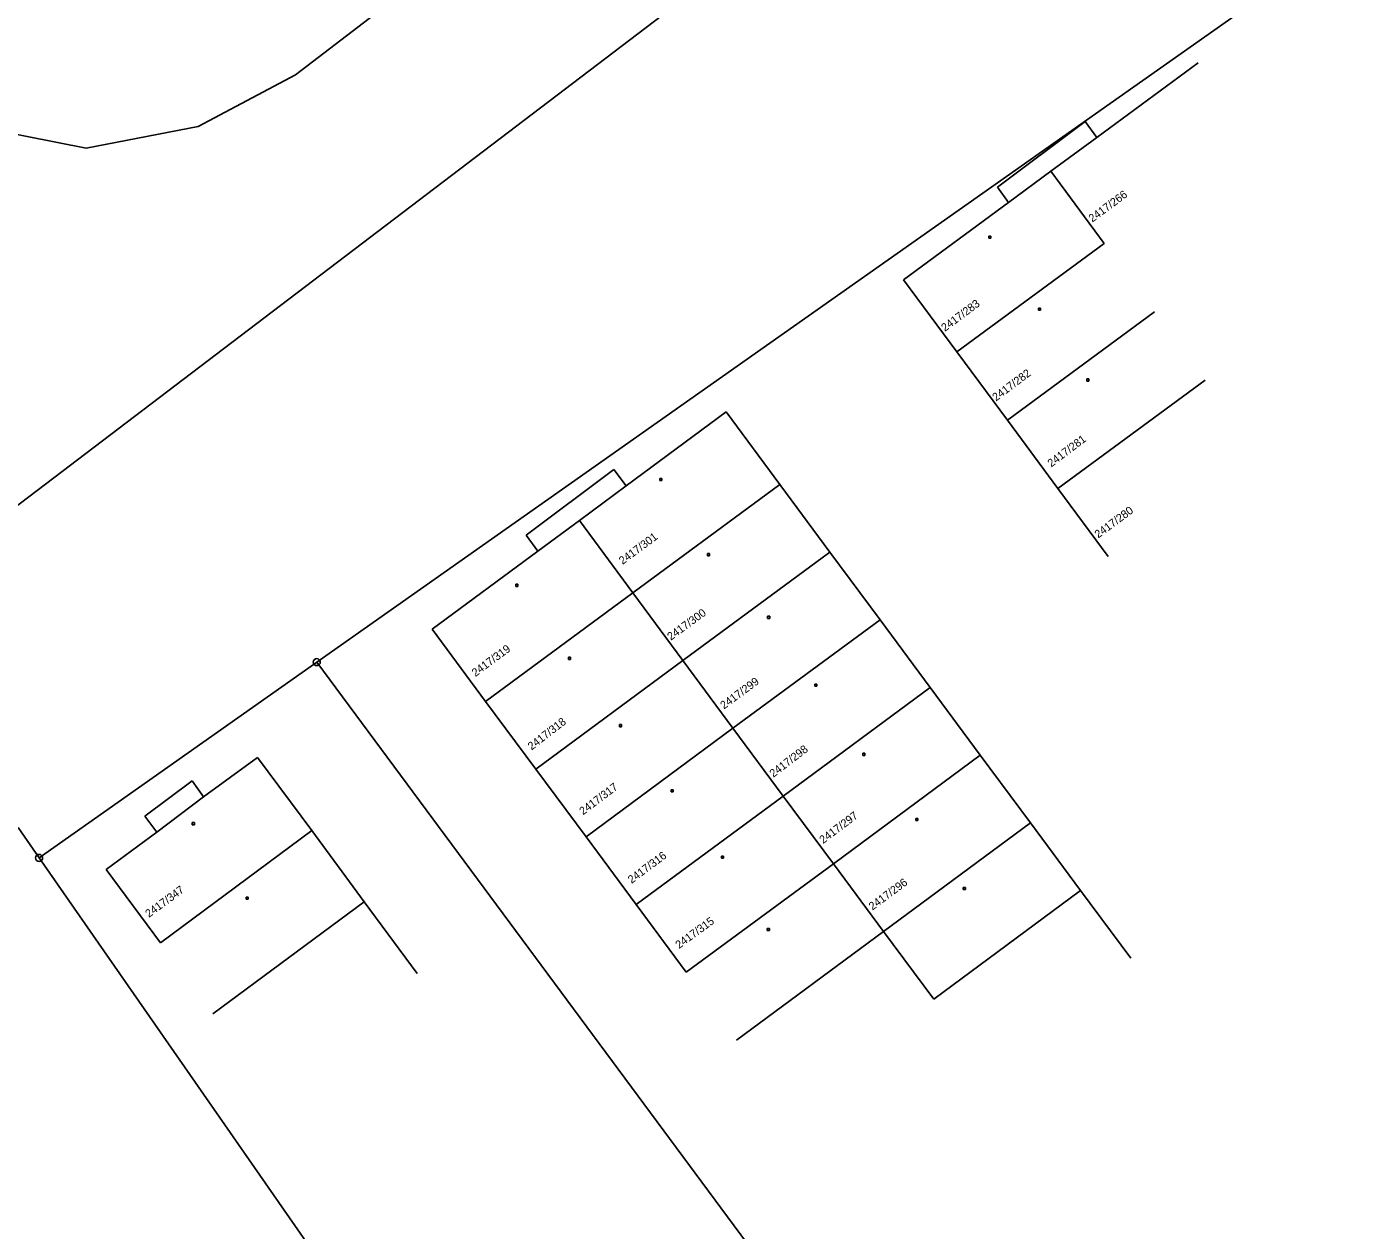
# Model space of a CAD drawing. Extents: x -609709 to -609357, y -1051535 to -1051131.
# Drawn here: x -609457.42 to -609409.61, y -1051497.4 to -1051454.54 of the extents above; entities that cross this region are included whole.
import ezdxf

# ---------------------------------------------------------------- set-up
doc = ezdxf.new("R2010")
doc.units = 0
doc.layers.add('Vrstva 10', color=7, linetype='Continuous')

msp = doc.modelspace()

# ---------------------------------------------------------------- linework, layer by layer
at = {"layer": 'Vrstva 10'}
for p, q in [((-609463.64, -1051476.07), (-609422.08, -1051444.46)), ((-609434.44, -1051445.99), (-609447.85, -1051456.25)), ((-609447.09, -1051477.17), (-609409.61, -1051450.76)), ((-609419.31, -1051458.49), (-609415.7, -1051455.83)), ((-609451.32, -1051458.09), (-609447.85, -1051456.25)), ((-609422.85, -1051460.26), (-609419.72, -1051457.92)), ((-609419.72, -1051457.92), (-609419.31, -1051458.49)), ((-609459.22, -1051458.09), (-609455.3, -1051458.86)), ((-609455.3, -1051458.86), (-609451.32, -1051458.09)), ((-609420.95, -1051459.69), (-609419.31, -1051458.49)), ((-609422.46, -1051460.8), (-609420.95, -1051459.69)), ((-609420.95, -1051459.69), (-609419.05, -1051462.26)), ((-609422.85, -1051460.26), (-609422.46, -1051460.8)), ((-609426.19, -1051463.55), (-609422.46, -1051460.8)), ((-609424.29, -1051466.12), (-609419.05, -1051462.26)), ((-609423.155, -1051461.995), (-609423.08, -1051461.995)), ((-609423.155, -1051462.07), (-609423.155, -1051461.995)), ((-609423.08, -1051462.07), (-609423.155, -1051462.07)), ((-609423.08, -1051461.995), (-609423.08, -1051462.07)), ((-609426.19, -1051463.55), (-609424.29, -1051466.12)), ((-609422.49, -1051468.55), (-609417.25, -1051464.7)), ((-609421.385, -1051464.565), (-609421.31, -1051464.565)), ((-609421.385, -1051464.64), (-609421.385, -1051464.565)), ((-609421.31, -1051464.64), (-609421.385, -1051464.64)), ((-609421.31, -1051464.565), (-609421.31, -1051464.64)), ((-609424.29, -1051466.12), (-609422.49, -1051468.55)), ((-609420.7, -1051470.98), (-609415.45, -1051467.13)), ((-609419.665, -1051467.085), (-609419.59, -1051467.085)), ((-609419.665, -1051467.16), (-609419.665, -1051467.085)), ((-609419.59, -1051467.085), (-609419.59, -1051467.16)), ((-609419.59, -1051467.16), (-609419.665, -1051467.16)), ((-609436.07, -1051470.89), (-609432.51, -1051468.26)), ((-609432.51, -1051468.26), (-609430.6, -1051470.84)), ((-609422.49, -1051468.55), (-609420.7, -1051470.98)), ((-609439.63, -1051472.65), (-609436.51, -1051470.31)), ((-609436.51, -1051470.31), (-609436.07, -1051470.89)), ((-609437.74, -1051472.13), (-609436.07, -1051470.89)), ((-609435.84, -1051474.7), (-609430.6, -1051470.84)), ((-609434.875, -1051470.625), (-609434.8, -1051470.625)), ((-609434.875, -1051470.7), (-609434.875, -1051470.625)), ((-609434.8, -1051470.7), (-609434.875, -1051470.7)), ((-609434.8, -1051470.625), (-609434.8, -1051470.7)), ((-609430.6, -1051470.84), (-609428.82, -1051473.25)), ((-609420.7, -1051470.98), (-609418.9, -1051473.41)), ((-609439.22, -1051473.22), (-609437.74, -1051472.13)), ((-609437.74, -1051472.13), (-609435.84, -1051474.7)), ((-609439.63, -1051472.65), (-609439.22, -1051473.22)), ((-609442.98, -1051475.99), (-609439.22, -1051473.22)), ((-609434.05, -1051477.11), (-609428.82, -1051473.25)), ((-609433.175, -1051473.305), (-609433.1, -1051473.305)), ((-609433.175, -1051473.38), (-609433.175, -1051473.305)), ((-609433.1, -1051473.305), (-609433.1, -1051473.38)), ((-609428.82, -1051473.25), (-609427.03, -1051475.66)), ((-609433.1, -1051473.38), (-609433.175, -1051473.38)), ((-609441.08, -1051478.57), (-609435.84, -1051474.7)), ((-609440.005, -1051474.395), (-609439.93, -1051474.395)), ((-609440.005, -1051474.47), (-609440.005, -1051474.395)), ((-609439.93, -1051474.47), (-609440.005, -1051474.47)), ((-609439.93, -1051474.395), (-609439.93, -1051474.47)), ((-609435.84, -1051474.7), (-609434.05, -1051477.11)), ((-609432.27, -1051479.52), (-609427.03, -1051475.66)), ((-609431.035, -1051475.535), (-609430.96, -1051475.535)), ((-609431.035, -1051475.61), (-609431.035, -1051475.535)), ((-609430.96, -1051475.61), (-609431.035, -1051475.61)), ((-609430.96, -1051475.535), (-609430.96, -1051475.61)), ((-609427.03, -1051475.66), (-609425.24, -1051478.07)), ((-609442.98, -1051475.99), (-609441.08, -1051478.57)), ((-609456.98, -1051484.14), (-609447.09, -1051477.17)), ((-609447.09, -1051477.17), (-609411.09, -1051525.77)), ((-609439.29, -1051480.98), (-609434.05, -1051477.11)), ((-609438.125, -1051476.995), (-609438.05, -1051476.995)), ((-609438.125, -1051477.07), (-609438.125, -1051476.995)), ((-609438.05, -1051477.07), (-609438.125, -1051477.07)), ((-609438.05, -1051476.995), (-609438.05, -1051477.07)), ((-609434.05, -1051477.11), (-609432.27, -1051479.52)), ((-609430.48, -1051481.94), (-609425.24, -1051478.07)), ((-609429.355, -1051477.955), (-609429.28, -1051477.955)), ((-609429.355, -1051478.03), (-609429.355, -1051477.955)), ((-609429.28, -1051478.03), (-609429.355, -1051478.03)), ((-609429.28, -1051477.955), (-609429.28, -1051478.03)), ((-609425.24, -1051478.07), (-609423.46, -1051480.48)), ((-609441.08, -1051478.57), (-609439.29, -1051480.98)), ((-609437.5, -1051483.39), (-609432.27, -1051479.52)), ((-609436.315, -1051479.395), (-609436.24, -1051479.395)), ((-609436.315, -1051479.47), (-609436.315, -1051479.395)), ((-609436.24, -1051479.47), (-609436.315, -1051479.47)), ((-609436.24, -1051479.395), (-609436.24, -1051479.47)), ((-609432.27, -1051479.52), (-609430.48, -1051481.94)), ((-609428.69, -1051484.35), (-609423.46, -1051480.48)), ((-609427.645, -1051480.415), (-609427.57, -1051480.415)), ((-609427.645, -1051480.49), (-609427.645, -1051480.415)), ((-609427.57, -1051480.49), (-609427.645, -1051480.49)), ((-609427.57, -1051480.415), (-609427.57, -1051480.49)), ((-609423.46, -1051480.48), (-609421.67, -1051482.89)), ((-609451.12, -1051481.97), (-609449.2, -1051480.56)), ((-609449.2, -1051480.56), (-609447.27, -1051483.17)), ((-609439.29, -1051480.98), (-609437.5, -1051483.39)), ((-609453.22, -1051482.65), (-609451.53, -1051481.4)), ((-609451.53, -1051481.4), (-609451.12, -1051481.97)), ((-609452.79, -1051483.23), (-609451.12, -1051481.97)), ((-609435.72, -1051485.8), (-609430.48, -1051481.94)), ((-609434.475, -1051481.715), (-609434.4, -1051481.715)), ((-609434.475, -1051481.79), (-609434.475, -1051481.715)), ((-609434.4, -1051481.79), (-609434.475, -1051481.79)), ((-609434.4, -1051481.715), (-609434.4, -1051481.79)), ((-609430.48, -1051481.94), (-609428.69, -1051484.35)), ((-609453.22, -1051482.65), (-609452.79, -1051483.23)), ((-609451.525, -1051482.885), (-609451.45, -1051482.885)), ((-609451.525, -1051482.96), (-609451.525, -1051482.885)), ((-609451.45, -1051482.885), (-609451.45, -1051482.96)), ((-609426.91, -1051486.76), (-609421.67, -1051482.89)), ((-609425.755, -1051482.735), (-609425.68, -1051482.735)), ((-609425.755, -1051482.81), (-609425.755, -1051482.735)), ((-609425.68, -1051482.81), (-609425.755, -1051482.81)), ((-609425.68, -1051482.735), (-609425.68, -1051482.81)), ((-609421.67, -1051482.89), (-609419.89, -1051485.3)), ((-609457.73, -1051483.06), (-609456.98, -1051484.14)), ((-609454.59, -1051484.56), (-609452.79, -1051483.23)), ((-609452.66, -1051487.17), (-609447.27, -1051483.17)), ((-609451.45, -1051482.96), (-609451.525, -1051482.96)), ((-609447.27, -1051483.17), (-609445.4, -1051485.7)), ((-609437.5, -1051483.39), (-609435.72, -1051485.8)), ((-609456.98, -1051484.14), (-609421.32, -1051535.36)), ((-609433.93, -1051488.21), (-609428.69, -1051484.35)), ((-609432.675, -1051484.075), (-609432.6, -1051484.075)), ((-609432.675, -1051484.15), (-609432.675, -1051484.075)), ((-609432.6, -1051484.15), (-609432.675, -1051484.15)), ((-609432.6, -1051484.075), (-609432.6, -1051484.15)), ((-609428.69, -1051484.35), (-609426.91, -1051486.76)), ((-609454.59, -1051484.56), (-609452.66, -1051487.17)), ((-609425.12, -1051489.17), (-609419.89, -1051485.3)), ((-609424.065, -1051485.195), (-609423.99, -1051485.195)), ((-609424.065, -1051485.27), (-609424.065, -1051485.195)), ((-609423.99, -1051485.27), (-609424.065, -1051485.27)), ((-609423.99, -1051485.195), (-609423.99, -1051485.27)), ((-609419.89, -1051485.3), (-609418.1, -1051487.71)), ((-609450.79, -1051489.7), (-609445.4, -1051485.7)), ((-609449.605, -1051485.535), (-609449.53, -1051485.535)), ((-609449.605, -1051485.61), (-609449.605, -1051485.535)), ((-609449.53, -1051485.61), (-609449.605, -1051485.61)), ((-609449.53, -1051485.535), (-609449.53, -1051485.61)), ((-609445.4, -1051485.7), (-609443.51, -1051488.26)), ((-609435.72, -1051485.8), (-609433.93, -1051488.21)), ((-609432.14, -1051490.63), (-609426.91, -1051486.76)), ((-609431.045, -1051486.655), (-609430.97, -1051486.655)), ((-609431.045, -1051486.73), (-609431.045, -1051486.655)), ((-609430.97, -1051486.73), (-609431.045, -1051486.73)), ((-609430.97, -1051486.655), (-609430.97, -1051486.73)), ((-609426.91, -1051486.76), (-609425.12, -1051489.17))]:
    msp.add_line(p, q, dxfattribs=at)
for centre, radius in [((-609447.09, -1051477.17), 0.125), ((-609447.09, -1051477.17), 0.0025), ((-609456.98, -1051484.14), 0.125), ((-609456.98, -1051484.14), 0.0025)]:
    msp.add_circle(centre, radius, dxfattribs=at)

# ---------------------------------------------------------------- texts
for s, rotation, p in [('2417/266', 36.5621, (-609419.47, -1051461.52)), ('2417/283', 36.7825, (-609424.72, -1051465.41)), ('2417/282', 36.8969, (-609422.9, -1051467.89)), ('2417/281', 37.128, (-609420.93, -1051470.24)), ('2417/280', 36.4572, (-609419.26, -1051472.77)), ('2417/301', 36.5716, (-609436.2, -1051473.71)), ('2417/300', 36.1519, (-609434.48, -1051476.41)), ('2417/319', 36.6249, (-609441.44, -1051477.7)), ('2417/299', 36.5125, (-609432.59, -1051478.86)), ('2417/318', 37.8461, (-609439.44, -1051480.32)), ('2417/298', 37.4181, (-609430.83, -1051481.29)), ('2417/317', 36.9976, (-609437.61, -1051482.63)), ('2417/297', 36.9094, (-609429.06, -1051483.65)), ('2417/316', 36.7897, (-609435.88, -1051485.07)), ('2417/347', 36.3475, (-609453.07, -1051486.28)), ('2417/296', 36.6171, (-609427.3, -1051486.02)), ('2417/315', 36.2173, (-609434.19, -1051487.39))]:
    msp.add_text(s, height=0.285, rotation=rotation, dxfattribs=at).set_placement(p)

doc.saveas('drawing.dxf')
